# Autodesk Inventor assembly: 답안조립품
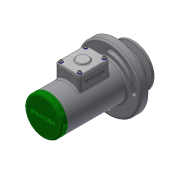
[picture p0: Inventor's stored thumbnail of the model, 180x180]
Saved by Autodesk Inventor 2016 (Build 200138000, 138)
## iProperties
Created: 2017-05
Part Number: 답안조립품
Document SubType Name: Weldment
Designer: KSEW
Weld Material: Welded Aluminum-6061
Author: KSEW
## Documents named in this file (20)
- D:\470507V1010\답안조립품.iam
- D:\470507V1010\본체.ipt
- D:\470507V1010\V-벨트풀리.ipt
- D:\470507V1010\너트 M10.ipt
- D:\470507V1010\멈춤링 15 x 1.ipt
- D:\470507V1010\멈춤링 35x1.6.ipt
- D:\470507V1010\베어링 15 x 35 x 11.ipt
- D:\470507V1010\볼트 M4 x 10.ipt
- D:\470507V1010\부시1.ipt
- D:\470507V1010\부시2.ipt
- D:\470507V1010\사이드 커버.ipt
- 사이드 커버.ipt
- D:\470507V1010\십자볼트 M3 x 10.ipt
- D:\470507V1010\오일 실 15 25 7.ipt
- D:\470507V1010\와셔 3x6.ipt
- D:\470507V1010\와셔 4x16.ipt
- D:\470507V1010\와셔 10x21.ipt
- D:\470507V1010\축.ipt
- D:\470507V1010\키 4 x 4 x 18.ipt
- D:\470507V1010\탑 커버.ipt
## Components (2 placed, 2 different names)
1. V-벨트풀리:1 — 각도:6
2. ISO 4017 M4 x 10:1 — 각도:7, 각도:8
## Component patterns: 구성요소 패턴 1:2 (2 elements)
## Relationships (3: Angle 3)
- 각도:6 [Angle]: V-벨트풀리:1
- 각도:7 [Angle]: ISO 4017 M4 x 10:1
- 각도:8 [Angle]: ISO 4017 M4 x 10:1
